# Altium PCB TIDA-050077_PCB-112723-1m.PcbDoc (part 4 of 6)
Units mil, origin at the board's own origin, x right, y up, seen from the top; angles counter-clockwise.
Board outline 3780 x 7750 mil, 16 copper layers (Top Layer, L2-Powet 1, L3-Power 2, L4-Power 3, L5-Power 4, L6-INT 1, L7-INT 2, L8-INT 3, L9-INT 4, L10-INT 5, L11-INT 6, L12-Power 5, L13-Power 6, L14-Power 7, L15-Power 8, Bottom Layer), stack 121.442 mil thick; 381 components, 136 nets, 958 pads, 3470 vias.
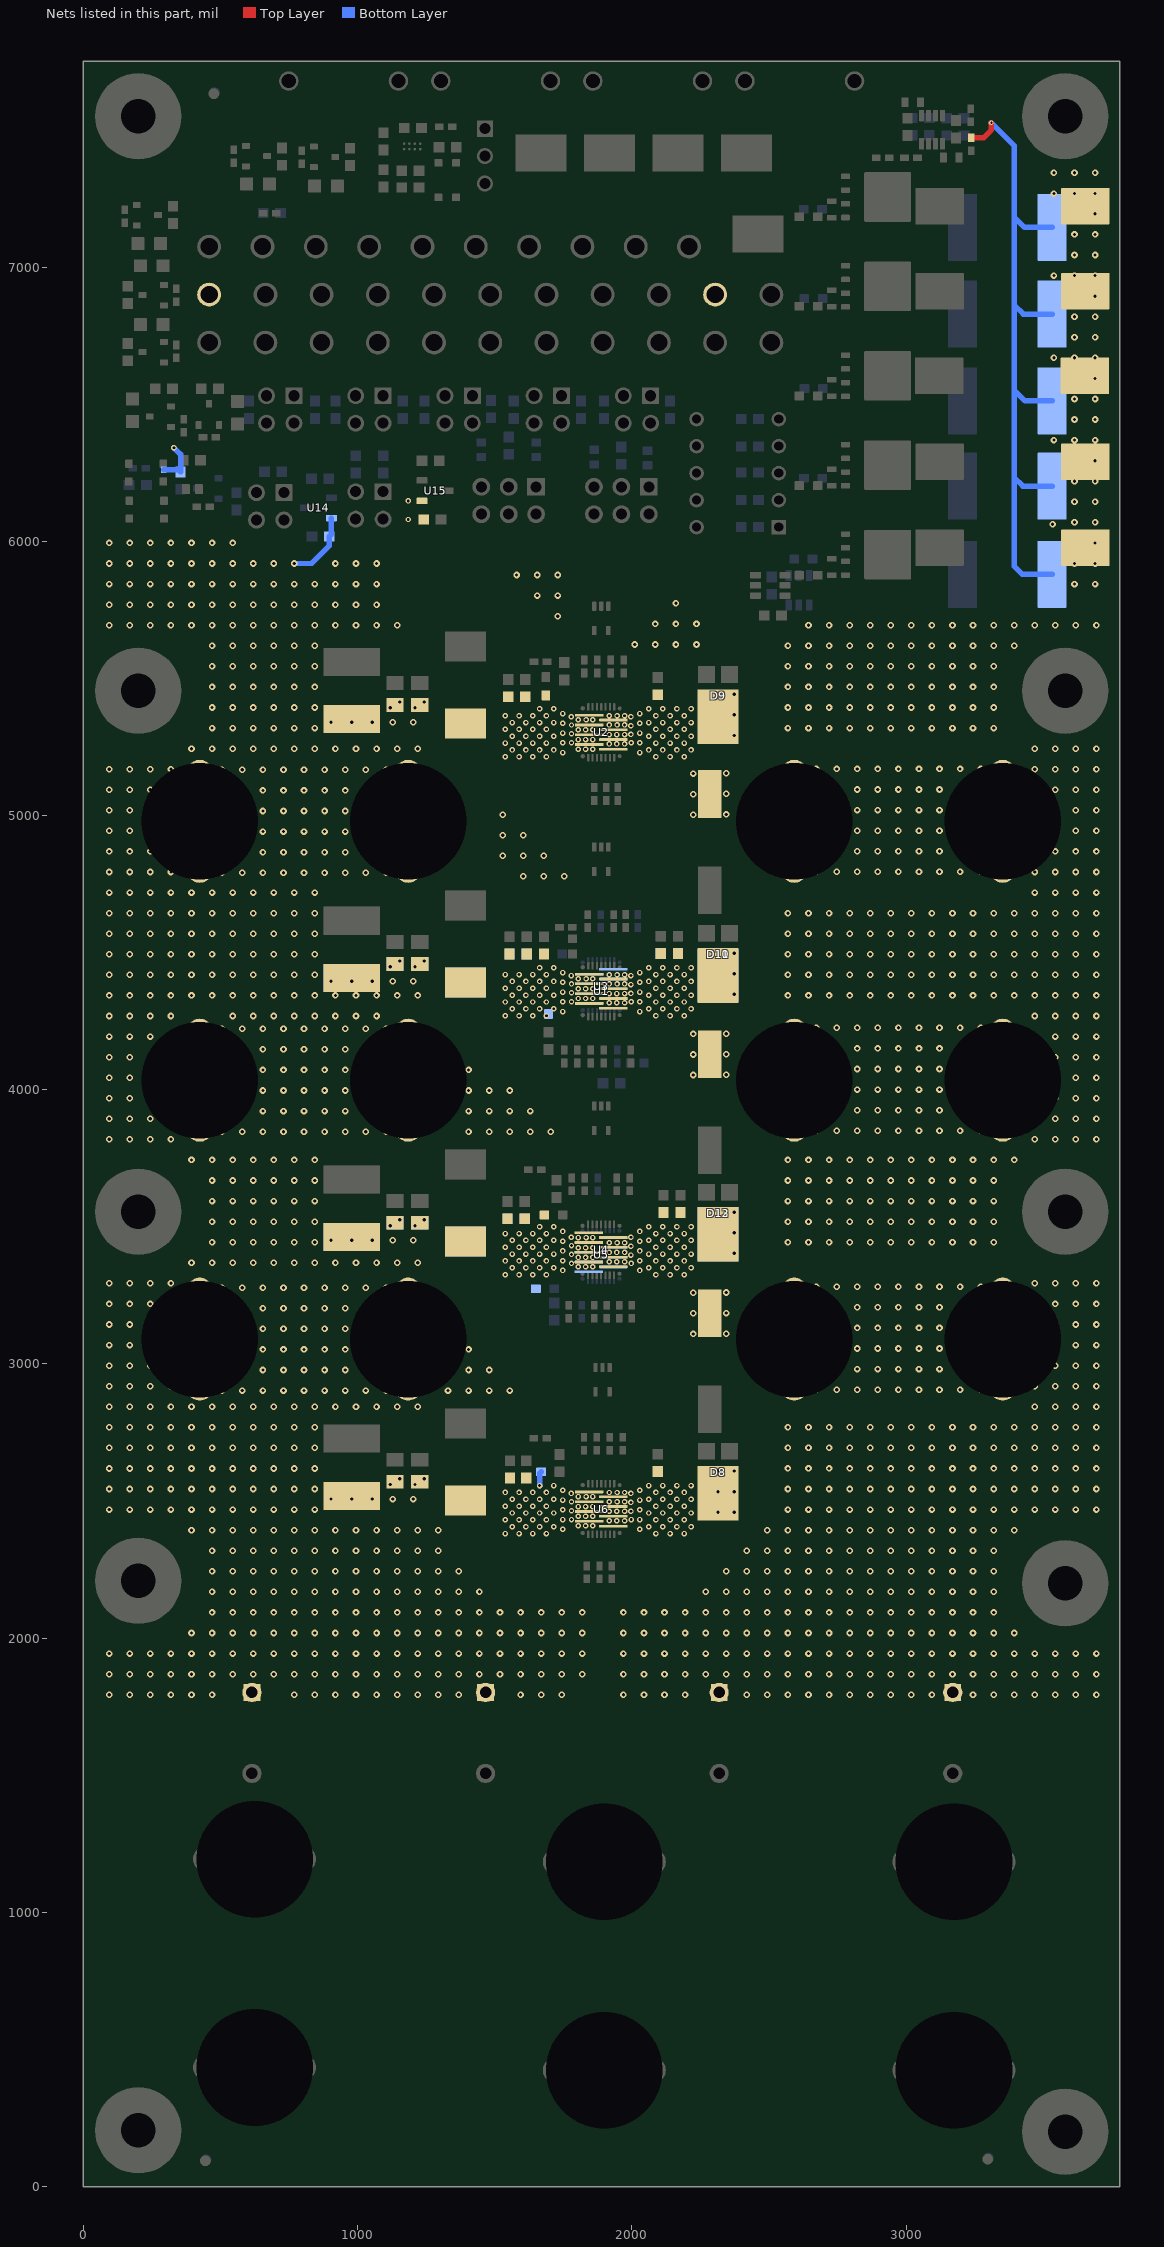
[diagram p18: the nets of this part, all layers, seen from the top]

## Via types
v1: diameter 24, hole 12, Top Layer to Bottom Layer, 2618 vias
v2: diameter 20, hole 10, Top Layer to Bottom Layer, 508 vias
v3: diameter 16, hole 8, Top Layer to Bottom Layer, tented both sides, 135 vias
v4: diameter 24, hole 12.1, Top Layer to Bottom Layer, 125 vias
v5: diameter 20, hole 10, Top Layer to Bottom Layer, tented both sides, 84 vias

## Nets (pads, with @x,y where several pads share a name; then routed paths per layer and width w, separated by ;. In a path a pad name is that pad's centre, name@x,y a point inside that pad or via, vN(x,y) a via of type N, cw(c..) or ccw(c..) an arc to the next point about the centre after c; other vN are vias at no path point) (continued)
VIN: C8.1 C15.1 C19.1 C20.1 C21.1 C31.1 C32.1 C33.1 C34.1 C35.1 C36.1 C37.1 C38.1 C39.1 C40.1 C41.1 C42.1 C43.1 C44.1 C45.1 C46.1 C47.1 C48.1 C49.1 C50.1 C53.1 C54.1 C57.1 C58.1 C61.1 C62.1 C65.1 C66.1 CO6.1 CO7.1 D2.1 D3.1 D4.1 D5.1 D6.1 D7.1 R41.1 R42.2 R46.1 R59.2 R64.2 R69.2 R74.2 R79.2 T5.1 T6.1 T7.1 T14.1 T15.1 TP16.1 U1.23 U1.24 U1.25 U1.26 U2.23 U2.24 U2.25 U2.26 U3.23 U3.24 U3.25 U3.26 U4.23 U4.24 U4.25 U4.26 U5.23 U5.24 U5.25 U5.26 U6.23 U6.24 U6.25 U6.26 U14.2 U15.2 | length 472.9
  Bottom Layer w20: R42.2@292.74,6259.99 347.42,6259.99 R46.1@354.41,6253 354.41,6316.63 v5(330.44,6340.61) ; v1(769.28,5918.9) 832.03,5918.9 896.5,5983.36 C8.1@896.5,6017.04 904.49,6025.04 U14.2@904.49,6084.64 ; v2(1663.71,2556.46) 1663.71,2601.32 R79.2@1668.95,2606.56
  other v1: 94.28,1793.9 169.28,1793.9 244.28,1793.9 319.28,1793.9 394.28,1793.9 469.28,1793.9 769.28,1793.9 844.28,1793.9 919.28,1793.9 994.28,1793.9 1069.28,1793.9 1144.28,1793.9 1219.28,1793.9 1294.28,1793.9 1369.28,1793.9 1594.28,1793.9 1669.28,1793.9 1744.28,1793.9 94.28,1868.9 169.28,1868.9 244.28,1868.9 319.28,1868.9 394.28,1868.9 469.28,1868.9 544.28,1868.9 619.28,1868.9 694.28,1868.9 769.28,1868.9 844.28,1868.9 919.28,1868.9 994.28,1868.9 1069.28,1868.9 1144.28,1868.9 1219.28,1868.9 1294.28,1868.9 1369.28,1868.9 1444.28,1868.9 1519.28,1868.9 1594.28,1868.9 1669.28,1868.9 1744.28,1868.9 1819.28,1868.9 94.28,1943.9 169.28,1943.9 244.28,1943.9 319.28,1943.9 394.28,1943.9 469.28,1943.9 544.28,1943.9 619.28,1943.9 694.28,1943.9 769.28,1943.9 844.28,1943.9 919.28,1943.9 994.28,1943.9 1069.28,1943.9 1144.28,1943.9 1219.28,1943.9 1294.28,1943.9 1369.28,1943.9 1444.28,1943.9 1519.28,1943.9 1594.28,1943.9 1669.28,1943.9 1744.28,1943.9 1819.28,1943.9 394.28,2018.9 469.28,2018.9 544.28,2018.9 619.28,2018.9 694.28,2018.9 769.28,2018.9 844.28,2018.9 919.28,2018.9 994.28,2018.9 1069.28,2018.9 1144.28,2018.9 1219.28,2018.9 1294.28,2018.9 1369.28,2018.9 1444.28,2018.9 1519.28,2018.9 1594.28,2018.9 1669.28,2018.9 1744.28,2018.9 1819.28,2018.9 469.28,2093.9 544.28,2093.9 619.28,2093.9 694.28,2093.9 769.28,2093.9 844.28,2093.9 919.28,2093.9 994.28,2093.9 1069.28,2093.9 1144.28,2093.9 1219.28,2093.9 1294.28,2093.9 1369.28,2093.9 1444.28,2093.9 1519.28,2093.9 1594.28,2093.9 1669.28,2093.9 1744.28,2093.9 1819.28,2093.9 469.28,2168.9 544.28,2168.9 619.28,2168.9 694.28,2168.9 769.28,2168.9 844.28,2168.9 919.28,2168.9 994.28,2168.9 1069.28,2168.9 1144.28,2168.9 1219.28,2168.9 1294.28,2168.9 1369.28,2168.9 1444.28,2168.9 469.28,2243.9 544.28,2243.9 619.28,2243.9 694.28,2243.9 769.28,2243.9 844.28,2243.9 919.28,2243.9 994.28,2243.9 1069.28,2243.9 1144.28,2243.9 1219.28,2243.9 1294.28,2243.9 1369.28,2243.9 469.28,2318.9 544.28,2318.9 619.28,2318.9 694.28,2318.9 769.28,2318.9 844.28,2318.9 919.28,2318.9 994.28,2318.9 1069.28,2318.9 1144.28,2318.9 1219.28,2318.9 1294.28,2318.9 394.28,2393.9 469.28,2393.9 544.28,2393.9 619.28,2393.9 694.28,2393.9 769.28,2393.9 844.28,2393.9 919.28,2393.9 994.28,2393.9 1069.28,2393.9 1144.28,2393.9 1219.28,2393.9 1294.28,2393.9 94.28,2468.9 169.28,2468.9 244.28,2468.9 319.28,2468.9 394.28,2468.9 469.28,2468.9 544.28,2468.9 619.28,2468.9 694.28,2468.9 769.28,2468.9 844.28,2468.9 903.28,2507.32 978.28,2507.32 1053.28,2507.32 1128.28,2507.32 1203.27,2507.32 94.28,2543.9 169.28,2543.9 244.28,2543.9 319.28,2543.9 394.28,2543.9 469.28,2543.9 544.28,2543.9 619.28,2543.9 694.28,2543.9 769.28,2543.9 844.28,2543.9 1119.47,2560.1 1209.47,2560.1 1153.57,2581.23 1243.57,2581.23 94.28,2618.9 169.28,2618.9 244.28,2618.9 319.28,2618.9 394.28,2618.9 469.28,2618.9 544.28,2618.9 619.28,2618.9 694.28,2618.9 769.28,2618.9 844.28,2618.9 94.28,2693.9 169.28,2693.9 244.28,2693.9 319.28,2693.9 394.28,2693.9 469.28,2693.9 544.28,2693.9 619.28,2693.9 694.28,2693.9 769.28,2693.9 844.28,2693.9 94.28,2768.9 169.28,2768.9 244.28,2768.9 319.28,2768.9 394.28,2768.9 469.28,2768.9 544.28,2768.9 619.28,2768.9 694.28,2768.9 769.28,2768.9 844.28,2768.9 94.28,2843.9 169.28,2843.9 244.28,2843.9 319.28,2843.9 394.28,2843.9 469.28,2843.9 544.28,2843.9 619.28,2843.9 694.28,2843.9 769.28,2843.9 844.28,2843.9 919.28,2843.9 994.28,2843.9 1069.28,2843.9 1144.28,2843.9 1219.28,2843.9 504.68,2903 579.68,2903 654.68,2903 729.68,2903 804.68,2903.01 879.68,2903.01 954.68,2903.01 1029.68,2903.01 1104.68,2903.01 1329.68,2903.01 1404.68,2903.01 1479.68,2903.01 1554.68,2903.01 94.28,2918.9 169.28,2918.9 244.28,2918.9 319.28,2918.9 504.68,2978 579.68,2978 654.68,2978 729.68,2978 804.68,2978.01 879.68,2978.01 954.68,2978.01 1029.68,2978.01 1104.68,2978.01 1329.68,2978.01 1404.68,2978.01 1479.68,2978.01 94.28,2993.9 169.28,2993.9 244.28,2993.9 319.28,2993.9 504.68,3053 579.68,3053 654.68,3053 729.68,3053.01 804.68,3053.01 879.68,3053.01 954.68,3053.01 1029.68,3053.01 1104.68,3053.01 1329.68,3053.01 1404.68,3053.01 94.28,3068.9 169.28,3068.9 244.28,3068.9 319.28,3068.9 504.68,3128 579.68,3128 654.68,3128.01 729.68,3128.01 804.68,3128.01 879.68,3128.01 954.68,3128.01 1029.68,3128.01 1104.68,3128.01 1329.68,3128.01 94.28,3143.9 169.28,3143.9 244.28,3143.9 319.28,3143.9 504.68,3203 579.68,3203 654.68,3203.01 729.68,3203.01 804.68,3203.01 879.68,3203.01 954.68,3203.01 1029.68,3203.01 1104.68,3203.01 94.28,3218.9 169.28,3218.9 244.28,3218.9 319.28,3218.9 504.68,3278 579.68,3278.01 654.68,3278.01 729.68,3278.01 804.68,3278.01 879.68,3278.01 954.68,3278.01 1029.68,3278.01 1104.68,3278.01 94.28,3293.9 169.28,3293.9 244.28,3293.9 319.28,3293.9 394.28,3368.9 469.28,3368.9 544.28,3368.9 619.28,3368.9 694.28,3368.9 769.28,3368.9 844.28,3368.9 919.28,3368.9 994.28,3368.9 1069.28,3368.9 1144.28,3368.9 1219.28,3368.9 469.28,3443.9 544.28,3443.9 619.28,3443.9 694.28,3443.9 769.28,3443.9 844.28,3443.9 903.28,3451.51 978.28,3451.51 1053.28,3451.51 1128.28,3451.51 1203.27,3451.51 1119.47,3504.29 1209.47,3504.29 469.28,3518.9 544.28,3518.9 619.28,3518.9 694.28,3518.9 769.28,3518.9 844.28,3518.9 1153.57,3525.42 1243.57,3525.42 469.28,3593.9 544.28,3593.9 619.28,3593.9 694.28,3593.9 769.28,3593.9 844.28,3593.9 469.28,3668.9 544.28,3668.9 619.28,3668.9 694.28,3668.9 769.28,3668.9 844.28,3668.9 394.28,3743.9 469.28,3743.9 544.28,3743.9 619.28,3743.9 694.28,3743.9 769.28,3743.9 844.28,3743.9 94.28,3818.9 169.28,3818.9 244.28,3818.9 319.28,3818.9 504.68,3847.2 579.68,3847.2 654.68,3847.2 729.68,3847.2 804.68,3847.2 879.68,3847.2 954.68,3847.2 1029.68,3847.2 1104.68,3847.2 1404.68,3847.2 1479.68,3847.2 1554.68,3847.2 1629.68,3847.2 1704.68,3847.2 94.28,3893.9 169.28,3893.9 244.28,3893.9 319.28,3893.9 504.68,3922.2 579.68,3922.2 654.68,3922.2 729.68,3922.2 804.68,3922.2 879.68,3922.2 954.68,3922.2 1029.68,3922.2 1104.68,3922.2 1404.68,3922.2 1479.68,3922.2 1554.68,3922.2 1629.68,3922.2 94.28,3968.9 169.28,3968.9 244.28,3968.9 319.28,3968.9 504.68,3997.2 579.68,3997.2 654.68,3997.2 729.68,3997.2 804.68,3997.2 879.68,3997.2 954.68,3997.2 1029.68,3997.2 1104.68,3997.2 1404.68,3997.2 1479.68,3997.2 1554.68,3997.2 94.28,4043.9 169.28,4043.9 244.28,4043.9 319.28,4043.9 504.68,4072.2 579.68,4072.2 654.68,4072.2 729.68,4072.2 804.68,4072.2 879.68,4072.2 954.68,4072.2 1029.68,4072.2 1104.68,4072.2 1404.68,4072.2 94.28,4118.9 169.28,4118.9 244.28,4118.9 319.28,4118.9 504.68,4147.2 579.68,4147.2 654.68,4147.2 729.68,4147.2 804.68,4147.2 879.68,4147.2 954.68,4147.2 1029.68,4147.2 1104.68,4147.2 94.28,4193.9 169.28,4193.9 244.28,4193.9 319.28,4193.9 504.68,4222.2 579.68,4222.2 654.68,4222.2 729.68,4222.2 804.68,4222.2 879.68,4222.2 954.68,4222.2 1029.68,4222.2 1104.68,4222.2 94.28,4268.9 169.28,4268.9 244.28,4268.9 319.28,4268.9 544.28,4268.9 619.28,4268.9 694.28,4268.9 769.28,4268.9 844.28,4268.9 919.28,4268.9 994.28,4268.9 1069.28,4268.9 94.28,4343.9 169.28,4343.9 244.28,4343.9 319.28,4343.9 394.28,4343.9 469.28,4343.9 544.28,4343.9 619.28,4343.9 694.28,4343.9 769.28,4343.9 844.28,4343.9 919.28,4343.9 994.28,4343.9 1069.28,4343.9 1144.28,4343.9 1219.28,4343.9 903.28,4395.71 978.28,4395.71 1053.28,4395.71 1128.28,4395.71 1203.28,4395.71 94.28,4418.9 169.28,4418.9 244.28,4418.9 319.28,4418.9 394.28,4418.9 469.28,4418.9 544.28,4418.9 619.28,4418.9 694.28,4418.9 769.28,4418.9 844.28,4418.9 1119.47,4448.49 1209.47,4448.49 1153.57,4469.62 1243.57,4469.62 94.28,4493.9 169.28,4493.9 244.28,4493.9 319.28,4493.9 394.28,4493.9 469.28,4493.9 544.28,4493.9 619.28,4493.9 694.28,4493.9 769.28,4493.9 844.28,4493.9 94.28,4568.9 169.28,4568.9 244.28,4568.9 319.28,4568.9 394.28,4568.9 469.28,4568.9 544.28,4568.9 619.28,4568.9 694.28,4568.9 769.28,4568.9 844.28,4568.9 94.28,4643.9 169.28,4643.9 244.28,4643.9 319.28,4643.9 394.28,4643.9 469.28,4643.9 544.28,4643.9 619.28,4643.9 694.28,4643.9 769.28,4643.9 844.28,4643.9 94.28,4718.9 169.28,4718.9 244.28,4718.9 319.28,4718.9 394.28,4718.9 469.28,4718.9 544.28,4718.9 619.28,4718.9 694.28,4718.9 769.28,4718.9 844.28,4718.9 1603.98,4777.96 1678.98,4777.96 1753.98,4777.96 504.68,4791.4 579.68,4791.4 654.68,4791.4 729.68,4791.4 804.68,4791.4 879.68,4791.4 954.68,4791.4 1029.68,4791.4 1104.68,4791.4 94.28,4793.9 169.28,4793.9 244.28,4793.9 319.28,4793.9 1528.98,4852.96 1603.98,4852.96 1678.98,4852.96 504.68,4866.4 579.68,4866.4 654.68,4866.4 729.68,4866.4 804.68,4866.4 879.68,4866.4 954.68,4866.4 1029.68,4866.4 1104.68,4866.4 94.28,4868.9 169.28,4868.9 244.28,4868.9 319.28,4868.9 1528.98,4927.96 1603.98,4927.96 504.68,4941.4 579.68,4941.4 654.68,4941.4 729.68,4941.4 804.68,4941.4 879.68,4941.4 954.68,4941.4 1029.68,4941.4 1104.68,4941.4 94.28,4943.9 169.28,4943.9 244.28,4943.9 319.28,4943.9 1528.98,5002.96 504.68,5016.4 579.68,5016.4 654.68,5016.4 729.68,5016.4 804.68,5016.4 879.68,5016.4 954.68,5016.4 1029.68,5016.4 1104.68,5016.4 94.28,5018.9 169.28,5018.9 244.28,5018.9 319.28,5018.9 504.68,5091.4 579.68,5091.4 654.68,5091.4 729.68,5091.4 804.68,5091.4 879.68,5091.4 954.68,5091.4 1029.68,5091.4 1104.68,5091.4 94.28,5093.9 169.28,5093.9 244.28,5093.9 319.28,5093.9 504.68,5166.4 579.68,5166.4 654.68,5166.4 729.68,5166.4 804.68,5166.4 879.68,5166.4 954.68,5166.4 1029.68,5166.4 1104.68,5166.4 94.28,5168.9 169.28,5168.9 244.28,5168.9 319.28,5168.9 394.28,5243.9 469.28,5243.9 544.28,5243.9 619.28,5243.9 694.28,5243.9 769.28,5243.9 844.28,5243.9 919.28,5243.9 994.28,5243.9 1069.28,5243.9 1144.28,5243.9 1219.28,5243.9 469.28,5318.9 544.28,5318.9 619.28,5318.9 694.28,5318.9 769.28,5318.9 844.28,5318.9 903.28,5339.91 978.28,5339.91 1053.28,5339.91 1128.28,5339.91 1203.27,5339.91 1119.47,5392.69 1209.47,5392.69 469.28,5393.9 544.28,5393.9 619.28,5393.9 694.28,5393.9 769.28,5393.9 844.28,5393.9 1153.57,5413.81 1243.57,5413.81 469.28,5468.9 544.28,5468.9 619.28,5468.9 694.28,5468.9 769.28,5468.9 844.28,5468.9 469.28,5543.9 544.28,5543.9 619.28,5543.9 694.28,5543.9 769.28,5543.9 844.28,5543.9 469.28,5618.9 544.28,5618.9 619.28,5618.9 694.28,5618.9 769.28,5618.9 844.28,5618.9 94.28,5693.9 169.28,5693.9 244.28,5693.9 319.28,5693.9 394.28,5693.9 469.28,5693.9 544.28,5693.9 619.28,5693.9 694.28,5693.9 769.28,5693.9 844.28,5693.9 919.28,5693.9 994.28,5693.9 1069.28,5693.9 1144.28,5693.9 1729.73,5726.9 94.28,5768.9 169.28,5768.9 244.28,5768.9 319.28,5768.9 394.28,5768.9 469.28,5768.9 544.28,5768.9 619.28,5768.9 694.28,5768.9 769.28,5768.9 844.28,5768.9 919.28,5768.9 994.28,5768.9 1069.28,5768.9 1654.73,5801.9 1729.73,5801.9 94.28,5843.9 169.28,5843.9 244.28,5843.9 319.28,5843.9 394.28,5843.9 469.28,5843.9 544.28,5843.9 619.28,5843.9 694.28,5843.9 769.28,5843.9 844.28,5843.9 919.28,5843.9 994.28,5843.9 1069.28,5843.9 1579.73,5876.9 1654.73,5876.9 1729.73,5876.9 94.28,5918.9 169.28,5918.9 244.28,5918.9 319.28,5918.9 394.28,5918.9 469.28,5918.9 544.28,5918.9 619.28,5918.9 694.28,5918.9 919.28,5918.9 994.28,5918.9 1069.28,5918.9 94.28,5993.9 169.28,5993.9 244.28,5993.9 319.28,5993.9 394.28,5993.9 469.28,5993.9 544.28,5993.9
  other v2: 1538.71,2381.46 1588.71,2381.46 1638.71,2381.46 1688.71,2381.46 1748.06,2396.79 1563.71,2406.46 1613.71,2406.46 1663.71,2406.46 1715.22,2406.46 1804.75,2409.62 1831.28,2409.62 1857.82,2409.62 1538.71,2431.46 1588.71,2431.46 1638.71,2431.46 1688.71,2431.46 1748.06,2432.35 1780.04,2432.35 1804.75,2444.25 1831.28,2444.25 1857.82,2444.25 1563.71,2456.46 1613.71,2456.46 1663.71,2456.46 1715.22,2456.46 1780.04,2465.13 1748.06,2467.91 1804.75,2479.87 1831.28,2479.87 1857.82,2479.87 1538.71,2481.46 1588.71,2481.46 1638.71,2481.46 1688.71,2481.46 1780.04,2497.39 1748.06,2503.47 1563.71,2506.46 1613.71,2506.46 1663.71,2506.46 1715.22,2506.46 1804.75,2516.48 1832.94,2516.48 1857.82,2516.48 1779.29,2527.85 1538.71,2531.46 1588.71,2531.46 1638.71,2531.46 1688.71,2531.46 1748.06,2539.03 1715.22,2556.46 1538.71,3325.66 1588.71,3325.66 1638.71,3325.66 1688.71,3325.66 1748.06,3340.99 1563.71,3350.66 1613.71,3350.66 1663.71,3350.66 1715.22,3350.66 1804.75,3354.83 1831.28,3354.83 1857.82,3354.83 1780.04,3366.55 1538.71,3375.66 1588.71,3375.66 1638.71,3375.66 1688.71,3375.66 1748.06,3376.55 1804.75,3388.45 1831.28,3388.45 1857.82,3388.45 1780.04,3399.33 1563.71,3400.66 1613.71,3400.66 1663.71,3400.66 1715.22,3400.66 1748.06,3412.1 1804.75,3424.07 1831.28,3424.07 1857.82,3424.07 1538.71,3425.66 1588.71,3425.66 1638.71,3425.66 1688.71,3425.66 1780.04,3431.58 1748.06,3447.66 1563.71,3450.66 1613.71,3450.66 1663.71,3450.66 1715.22,3450.66 1804.75,3460.68 1832.94,3460.68 1857.82,3460.68 1779.29,3462.05 1538.71,3475.66 1588.71,3475.66 1638.71,3475.66 1688.71,3475.66 1748.06,3483.22 1663.71,3500.66 1715.22,3500.66 1538.71,4269.86 1588.71,4269.86 1638.71,4269.86 1688.71,4269.86 1748.06,4285.18 1563.71,4294.86 1613.71,4294.86 1663.71,4294.86 1715.22,4294.86 1538.71,4319.86 1588.71,4319.86 1638.71,4319.86 1688.71,4319.86 1748.06,4320.74 1780.04,4320.74 1804.75,4332.64 1831.28,4332.64 1857.82,4332.64 1563.71,4344.86 1613.71,4344.86 1663.71,4344.86 1715.22,4344.86 1780.04,4353.52 1748.06,4356.3 1804.75,4368.26 1831.28,4368.26 1857.82,4368.26 1538.71,4369.86 1588.71,4369.86 1638.71,4369.86 1688.71,4369.86 1780.04,4385.78 1748.06,4391.86 1563.71,4394.86 1613.71,4394.86 1663.71,4394.86 1715.22,4394.86 1804.75,4404.87 1832.94,4404.87 1857.82,4404.87 1779.29,4416.24 1538.71,4419.86 1588.71,4419.86 1638.71,4419.86 1688.71,4419.86 1748.06,4427.42 1663.71,4444.86 1715.22,4444.86 1538.71,5214.05 1588.71,5214.05 1638.71,5214.05 1688.71,5214.05 1748.06,5229.38 1563.71,5239.05 1613.71,5239.05 1663.71,5239.05 1715.22,5239.05 1804.75,5241.21 1831.28,5241.21 1857.82,5241.21 1538.71,5264.05 1588.71,5264.05 1638.71,5264.05 1688.71,5264.05 1748.06,5264.94 1780.04,5264.94 1804.75,5276.84 1831.28,5276.84 1857.82,5276.84 1563.71,5289.05 1613.71,5289.05 1663.71,5289.05 1715.22,5289.05 1780.04,5297.72 1748.06,5300.5 1804.75,5312.46 1831.28,5312.46 1857.82,5312.46 1538.71,5314.05 1588.71,5314.05 1638.71,5314.05 1688.71,5314.05 1780.04,5329.97 1748.06,5336.05 1563.71,5339.05 1613.71,5339.05 1663.71,5339.05 1715.22,5339.05 1804.75,5349.07 1832.94,5349.07 1857.82,5349.07 1779.29,5360.44 1538.71,5364.05 1588.71,5364.05 1638.71,5364.05 1688.71,5364.05 1748.06,5371.61 1663.71,5389.05 1715.22,5389.05
  other v5: 1184.33,6079.37 1184.33,6146.97
VOUT: C22.1 C23.1 C24.1 C51.1 C55.1 C59.1 C63.1 C67.1 CO1.1 CO2.1 CO3.1 CO4.1 CO5.1 D8.3 D9.3 D10.3 D11.3 D12.3 D13.3 R23.2 R24.2 R25.2 R26.2 R27.2 R28.2 R29.2 R30.2 R31.2 R32.2 RZ1.2 T1.1 T2.1 T8.1 T9.1 T10.1 TP22.1 U1.10 U1.11 U1.12 U1.13 U2.10 U2.11 U2.12 U2.13 U3.10 U3.11 U3.12 U3.13 U4.10 U4.11 U4.12 U4.13 U5.10 U5.11 U5.12 U5.13 U6.10 U6.11 U6.12 U6.13 | length 2525.6
  Top Layer w20: RZ1.2@3237.75,7471.09 3282.31,7471.09 3311.29,7500.08 v3(3311.29,7526.09)
  Bottom Layer w20: v3(3311.29,7526.09) 3394.28,7443.1 3394.28,7182.75 ; R31.2@3532.55,5879.5 3424.33,5879.5 3394.28,5909.55 3394.28,6232.49 ; R30.2@3532.55,6200.81 3425.96,6200.81 3394.28,6232.49 ; R29.2@3532.55,6512.12 3434.49,6512.12 3394.28,6552.33 ; R28.2@3532.55,6828.44 3427.57,6828.44 3394.28,6861.73 ; R32.2@3532.55,7144.75 3432.28,7144.75 3394.28,7182.75 ; 3394.28,6232.49 3394.28,6552.33 ; 3394.28,6552.33 3394.28,6861.73 ; 3394.28,6861.73 3394.28,7182.75
  other v1: 1969.28,1793.91 2044.28,1793.91 2119.28,1793.91 2194.28,1793.91 2419.28,1793.91 2494.28,1793.91 2569.28,1793.91 2644.28,1793.91 2719.28,1793.91 2794.28,1793.91 2869.28,1793.91 2944.28,1793.91 3019.28,1793.91 3094.28,1793.91 3244.28,1793.91 3319.28,1793.91 3394.28,1793.91 3469.28,1793.91 3544.28,1793.91 3619.28,1793.91 3694.28,1793.91 1969.28,1868.91 2044.28,1868.91 2119.28,1868.91 2194.28,1868.91 2269.28,1868.91 2344.28,1868.91 2419.28,1868.91 2494.28,1868.91 2569.28,1868.91 2644.28,1868.91 2719.28,1868.91 2794.28,1868.91 2869.28,1868.91 2944.28,1868.91 3019.28,1868.91 3094.28,1868.91 3169.28,1868.91 3244.28,1868.91 3319.28,1868.91 3394.28,1868.91 3469.28,1868.91 3544.28,1868.91 3619.28,1868.91 3694.28,1868.91 1969.28,1943.91 2044.28,1943.91 2119.28,1943.91 2194.28,1943.91 2269.28,1943.91 2344.28,1943.91 2419.28,1943.91 2494.28,1943.91 2569.28,1943.91 2644.28,1943.91 2719.28,1943.91 2794.28,1943.91 2869.28,1943.91 2944.28,1943.91 3019.28,1943.91 3094.28,1943.91 3169.28,1943.91 3244.28,1943.91 3319.28,1943.91 3394.28,1943.91 3469.28,1943.91 3544.28,1943.91 3619.28,1943.91 3694.28,1943.91 1969.28,2018.91 2044.28,2018.91 2119.28,2018.91 2194.28,2018.91 2269.28,2018.91 2344.28,2018.91 2419.28,2018.91 2494.28,2018.91 2569.28,2018.91 2644.28,2018.91 2719.28,2018.91 2794.28,2018.91 2869.28,2018.91 2944.28,2018.91 3019.28,2018.91 3094.28,2018.91 3169.28,2018.91 3244.28,2018.91 3319.28,2018.91 3394.28,2018.91 1969.28,2093.91 2044.28,2093.91 2119.28,2093.91 2194.28,2093.91 2269.28,2093.91 2344.28,2093.91 2419.28,2093.91 2494.28,2093.91 2569.28,2093.91 2644.28,2093.91 2719.28,2093.91 2794.28,2093.91 2869.28,2093.91 2944.28,2093.91 3019.28,2093.91 3094.28,2093.91 3169.28,2093.91 3244.28,2093.91 3319.28,2093.91 2269.28,2168.91 2344.28,2168.91 2419.28,2168.91 2494.28,2168.91 2569.28,2168.91 2644.28,2168.91 2719.28,2168.91 2794.28,2168.9 2869.28,2168.9 2944.28,2168.9 3019.28,2168.9 3094.28,2168.9 3169.28,2168.9 3244.28,2168.9 3319.28,2168.9 2344.28,2243.9 2419.28,2243.9 2494.28,2243.9 2569.28,2243.9 2644.28,2243.9 2719.28,2243.9 2794.28,2243.9 2869.28,2243.9 2944.28,2243.9 3019.28,2243.9 3094.28,2243.9 3169.28,2243.9 3244.28,2243.9 3319.28,2243.9 2419.28,2318.9 2494.28,2318.9 2569.28,2318.9 2644.28,2318.9 2719.28,2318.9 2794.28,2318.9 2869.28,2318.9 2944.28,2318.9 3019.28,2318.9 3094.28,2318.9 3169.28,2318.9 3244.28,2318.9 3319.28,2318.9 2494.28,2393.9 2569.28,2393.9 2644.28,2393.9 2719.28,2393.9 2794.28,2393.9 2869.28,2393.9 2944.28,2393.9 3019.28,2393.9 3094.28,2393.9 3169.28,2393.9 3244.28,2393.9 3319.28,2393.9 3394.28,2393.9 2314.28,2459.45 2373.55,2459.45 2569.28,2468.9 2644.28,2468.9 2719.28,2468.9 2794.28,2468.9 2869.28,2468.9 2944.28,2468.9 3019.28,2468.9 3094.28,2468.9 3169.28,2468.9 3244.28,2468.9 3319.28,2468.9 3394.28,2468.9 3469.28,2468.9 3544.28,2468.9 3619.28,2468.9 3694.28,2468.9 2314.28,2534.45 2373.55,2534.45 2569.28,2543.9 2644.28,2543.9 2719.28,2543.9 2794.28,2543.9 2869.28,2543.9 2944.28,2543.9 3019.28,2543.9 3094.28,2543.9 3169.28,2543.9 3244.28,2543.9 3319.28,2543.9 3394.28,2543.9 3469.28,2543.9 3544.28,2543.9 3619.28,2543.9 3694.28,2543.9 2314.28,2609.44 2373.55,2609.44 2569.28,2618.9 2644.28,2618.9 2719.28,2618.9 2794.28,2618.9 2869.28,2618.9 2944.28,2618.9 3019.28,2618.9 3094.28,2618.9 3169.28,2618.9 3244.28,2618.9 3319.28,2618.9 3394.28,2618.9 3469.28,2618.9 3544.28,2618.9 3619.28,2618.9 3694.28,2618.9 2569.28,2693.9 2644.28,2693.9 2719.28,2693.9 2794.28,2693.9 2869.28,2693.9 2944.28,2693.9 3019.28,2693.9 3094.28,2693.9 3169.28,2693.9 3244.28,2693.9 3319.28,2693.9 3394.28,2693.9 3469.28,2693.9 3544.28,2693.9 3619.28,2693.9 3694.28,2693.9 2569.28,2768.9 2644.28,2768.9 2719.28,2768.9 2794.28,2768.9 2869.28,2768.9 2944.28,2768.9 3019.28,2768.9 3094.28,2768.9 3169.28,2768.9 3244.28,2768.9 3319.28,2768.9 3394.28,2768.9 3469.28,2768.9 3544.28,2768.9 3619.28,2768.9 3694.28,2768.9 3469.28,2843.9 3544.28,2843.9 3619.28,2843.9 3694.28,2843.9 2672.09,2906.4 2747.09,2906.4 2822.09,2906.4 2897.09,2906.4 2972.1,2906.4 3047.1,2906.4 3122.1,2906.4 3197.1,2906.4 3272.1,2906.4 3469.28,2918.9 3544.28,2918.9 3619.28,2918.9 3694.28,2918.9 2672.09,2981.4 2747.09,2981.4 2822.09,2981.4 2897.09,2981.4 2972.09,2981.4 3047.1,2981.4 3122.1,2981.4 3197.1,2981.4 3272.1,2981.4 3469.28,2993.9 3544.28,2993.9 3619.28,2993.9 3694.28,2993.9 2672.09,3056.4 2747.09,3056.4 2822.09,3056.4 2897.09,3056.4 2972.1,3056.4 3047.1,3056.4 3122.1,3056.4 3197.1,3056.4 3272.1,3056.4 3469.28,3068.9 3544.28,3068.9 3619.28,3068.9 3694.28,3068.9 2224.28,3109.37 2344.28,3110.43 2672.09,3131.4 2747.09,3131.4 2822.09,3131.4 2897.09,3131.4 2972.09,3131.4 3047.1,3131.4 3122.1,3131.4 3197.1,3131.4 3272.1,3131.4 3469.28,3143.9 3544.28,3143.9 3619.28,3143.9 3694.28,3143.9 2224.28,3184.37 2344.28,3185.43 2672.09,3206.4 2747.09,3206.4 2822.09,3206.4 2897.09,3206.4 2972.09,3206.4 3047.09,3206.4 3122.1,3206.4 3197.1,3206.4 3272.1,3206.4 3469.28,3218.9 3544.28,3218.9 3619.28,3218.9 3694.28,3218.9 2224.28,3259.37 2344.28,3260.42 2672.09,3281.4 2747.09,3281.4 2822.09,3281.4 2897.09,3281.4 2972.09,3281.4 3047.1,3281.4 3122.1,3281.4 3197.1,3281.4 3272.1,3281.4 3469.28,3293.9 3544.28,3293.9 3619.28,3293.9 3694.28,3293.9 2373.55,3403.64 2569.28,3443.9 2644.28,3443.9 2719.28,3443.9 2794.28,3443.9 2869.28,3443.9 2944.28,3443.9 3019.28,3443.9 3094.28,3443.9 3169.28,3443.9 3244.28,3443.9 3319.28,3443.9 2373.55,3478.64 2569.28,3518.9 2644.28,3518.9 2719.28,3518.9 2794.28,3518.9 2869.28,3518.9 2944.28,3518.9 3019.28,3518.9 3094.28,3518.9 3169.28,3518.9 3244.28,3518.9 3319.28,3518.9 2373.55,3553.64 2569.28,3593.9 2644.28,3593.9 2719.28,3593.9 2794.28,3593.9 2869.28,3593.9 2944.28,3593.9 3019.28,3593.9 3094.28,3593.9 3169.28,3593.9 3244.28,3593.9 3319.28,3593.9 2569.28,3668.9 2644.28,3668.9 2719.28,3668.9 2794.28,3668.9 2869.28,3668.9 2944.28,3668.9 3019.28,3668.9 3094.28,3668.9 3169.28,3668.9 3244.28,3668.9 3319.28,3668.9 2569.28,3743.9 2644.28,3743.9 2719.28,3743.9 2794.28,3743.9 2869.28,3743.9 2944.28,3743.9 3019.28,3743.9 3094.28,3743.9 3169.28,3743.9 3244.28,3743.9 3319.28,3743.9 3394.28,3743.9 3469.28,3818.9 3544.28,3818.9 3619.28,3818.9 3694.28,3818.9 2672.09,3850.59 2747.09,3850.59 2822.09,3850.59 2897.09,3850.59 2972.1,3850.59 3047.1,3850.59 3122.1,3850.59 3197.1,3850.59 3272.1,3850.59 3469.28,3893.9 3544.28,3893.9 3619.28,3893.9 3694.28,3893.9 2672.09,3925.59 2747.09,3925.59 2822.09,3925.59 2897.09,3925.59 2972.09,3925.59 3047.1,3925.59 3122.1,3925.59 3197.1,3925.59 3272.1,3925.59 3469.28,3968.9 3544.28,3968.9 3619.28,3968.9 3694.28,3968.9 2672.09,4000.59 2747.09,4000.59 2822.09,4000.59 2897.09,4000.59 2972.1,4000.59 3047.1,4000.59 3122.1,4000.59 3197.1,4000.59 3272.1,4000.59 3469.28,4043.9 3544.28,4043.9 3619.28,4043.9 3694.28,4043.9 2224.28,4053.57 2344.28,4054.62 2672.09,4075.59 2747.09,4075.59 2822.09,4075.59 2897.09,4075.59 2972.09,4075.59 3047.1,4075.59 3122.1,4075.59 3197.1,4075.59 3272.1,4075.59 3469.28,4118.9 3544.28,4118.9 3619.28,4118.9 3694.28,4118.9 2224.28,4128.57 2344.28,4129.62 2672.09,4150.59 2747.09,4150.59 2822.09,4150.59 2897.09,4150.59 2972.09,4150.59 3047.09,4150.59 3122.1,4150.59 3197.1,4150.59 3272.1,4150.59 3469.28,4193.9 3544.28,4193.9 3619.28,4193.9 3694.28,4193.9 2224.28,4203.57 2344.28,4204.62 2672.09,4225.59 2747.09,4225.59 2822.09,4225.59 2897.09,4225.59 2972.09,4225.59 3047.1,4225.59 3122.1,4225.59 3197.1,4225.59 3272.1,4225.59 3469.28,4268.9 3544.28,4268.9 3619.28,4268.9 3694.28,4268.9 2569.28,4343.9 2644.28,4343.9 2719.28,4343.9 2794.28,4343.9 2869.28,4343.9 2944.28,4343.9 3019.28,4343.9 3094.28,4343.9 3169.28,4343.9 3244.28,4343.9 3319.28,4343.9 3394.28,4343.9 3469.28,4343.9 3544.28,4343.9 3619.28,4343.9 3694.28,4343.9 2373.55,4347.84 2569.28,4418.9 2644.28,4418.9 2719.28,4418.9 2794.28,4418.9 2869.28,4418.9 2944.28,4418.9 3019.28,4418.9 3094.28,4418.9 3169.28,4418.9 3244.28,4418.9 3319.28,4418.9 3394.28,4418.9 3469.28,4418.9 3544.28,4418.9 3619.28,4418.9 3694.28,4418.9 2373.55,4422.84 2569.28,4493.9 2644.28,4493.9 2719.28,4493.9 2794.28,4493.9 2869.28,4493.9 2944.28,4493.9 3019.28,4493.9 3094.28,4493.9 3169.28,4493.9 3244.28,4493.9 3319.28,4493.9 3394.28,4493.9 3469.28,4493.9 3544.28,4493.9 3619.28,4493.9 3694.28,4493.9 2373.55,4497.83 2569.28,4568.9 2644.28,4568.9 2719.28,4568.9 2794.28,4568.9 2869.28,4568.9 2944.28,4568.9 3019.28,4568.9 3094.28,4568.9 3169.28,4568.9 3244.28,4568.9 3319.28,4568.9 3394.28,4568.9 3469.28,4568.9 3544.28,4568.9 3619.28,4568.9 3694.28,4568.9 2569.28,4643.9 2644.28,4643.9 2719.28,4643.9 2794.28,4643.9 2869.28,4643.9 2944.28,4643.9 3019.28,4643.9 3094.28,4643.9 3169.28,4643.9 3244.28,4643.9 3319.28,4643.9 3394.28,4643.9 3469.28,4643.9 3544.28,4643.9 3619.28,4643.9 3694.28,4643.9 3469.28,4718.9 3544.28,4718.9 3619.28,4718.9 3694.28,4718.9 3469.28,4793.9 3544.28,4793.9 3619.28,4793.9 3694.28,4793.9 2672.09,4794.79 2747.09,4794.79 2822.09,4794.79 2897.09,4794.79 2972.1,4794.79 3047.1,4794.79 3122.1,4794.79 3197.1,4794.79 3272.1,4794.79 3469.28,4868.9 3544.28,4868.9 3619.28,4868.9 3694.28,4868.9 2672.09,4869.79 2747.09,4869.79 2822.09,4869.79 2897.09,4869.79 2972.09,4869.79 3047.1,4869.79 3122.1,4869.79 3197.1,4869.79 3272.1,4869.79 3469.28,4943.9 3544.28,4943.9 3619.28,4943.9 3694.28,4943.9 2672.09,4944.79 2747.09,4944.79 2822.09,4944.79 2897.09,4944.79 2972.1,4944.79 3047.1,4944.79 3122.1,4944.79 3197.1,4944.79 3272.1,4944.79 2224.28,5002.84 2344.28,5003.9 3469.28,5018.9 3544.28,5018.9 3619.28,5018.9 3694.28,5018.9 2672.09,5019.79 2747.09,5019.79 2822.09,5019.79 2897.09,5019.79 2972.09,5019.79 3047.1,5019.79 3122.1,5019.79 3197.1,5019.79 3272.1,5019.79 2224.28,5077.84 2344.28,5078.9 3469.28,5093.9 3544.28,5093.9 3619.28,5093.9 3694.28,5093.9 2672.09,5094.79 2747.09,5094.79 2822.09,5094.79 2897.09,5094.79 2972.09,5094.79 3047.09,5094.79 3122.1,5094.79 3197.1,5094.79 3272.1,5094.79 2224.28,5152.84 2344.28,5153.9 3469.28,5168.9 3544.28,5168.9 3619.28,5168.9 3694.28,5168.9 2672.09,5169.79 2747.09,5169.79 2822.09,5169.79 2897.09,5169.79 2972.09,5169.79 3047.1,5169.79 3122.1,5169.79 3197.1,5169.79 3272.1,5169.79 3469.28,5243.9 3544.28,5243.9 3619.28,5243.9 3694.28,5243.9 2373.55,5292.04 2569.28,5318.9 2644.28,5318.9 2719.28,5318.9 2794.28,5318.9 2869.28,5318.9 2944.28,5318.9 3019.28,5318.9 3094.28,5318.9 3169.28,5318.9 3244.28,5318.9 3319.28,5318.9 2373.55,5367.03 2569.28,5393.9 2644.28,5393.9 2719.28,5393.9 2794.28,5393.9 2869.28,5393.9 2944.28,5393.9 3019.28,5393.9 3094.28,5393.9 3169.28,5393.9 3244.28,5393.9 3319.28,5393.9 2373.55,5442.03 2569.28,5468.9 2644.28,5468.9 2719.28,5468.9 2794.28,5468.9 2869.28,5468.9 2944.28,5468.9 3019.28,5468.9 3094.28,5468.9 3169.28,5468.9 3244.28,5468.9 3319.28,5468.9 2569.28,5543.9 2644.28,5543.9 2719.28,5543.9 2794.28,5543.9 2869.28,5543.9 2944.28,5543.9 3019.28,5543.9 3094.28,5543.9 3169.28,5543.9 3244.28,5543.9 3319.28,5543.9 2569.28,5618.9 2644.28,5618.9 2719.28,5618.9 2794.28,5618.9 2869.28,5618.9 2944.28,5618.9 3019.28,5618.9 3094.28,5618.9 3169.28,5618.9 3244.28,5618.9 3319.28,5618.9 3394.28,5618.9 2010.79,5623.5 2085.79,5623.5 2160.79,5623.5 2235.79,5623.5 2644.28,5693.9 2719.28,5693.9 2794.28,5693.9 2869.28,5693.9 2944.28,5693.9 3019.28,5693.9 3094.28,5693.9 3169.28,5693.9 3244.28,5693.9 3319.28,5693.9 3394.28,5693.9 3469.28,5693.9 3544.28,5693.9 3619.28,5693.9 3694.28,5693.9 2085.79,5698.5 2160.79,5698.5 2235.79,5698.5 2160.79,5773.5 3614.28,5843.9 3689.28,5843.9 3614.28,5918.9 3689.28,5918.9 3689.28,5993.9 3534.28,6061.77 3614.28,6068.9 3689.28,6068.9 3614.28,6143.9 3689.28,6143.9 3614.28,6218.9 3689.28,6218.9 3689.28,6293.9 3539.28,6368.9 3614.28,6368.9 3689.28,6368.9 3614.28,6443.9 3689.28,6443.9 3614.28,6518.9 3689.28,6518.9 3689.28,6593.9 3539.28,6668.9 3614.28,6668.9 3689.28,6668.9 3614.28,6743.9 3689.28,6743.9 3614.28,6818.9 3689.28,6818.9 3689.28,6893.9 3539.28,6968.9 3614.28,6968.9 3689.28,6968.9 3614.28,7043.9 3689.28,7043.9 3614.28,7118.9 3689.28,7118.9 3689.28,7193.9 3539.28,7267.95 3614.28,7267.95 3689.28,7267.95 3539.28,7343.9 3614.28,7343.9 3689.28,7343.9
  other v2: 2088.07,2381.46 2139.58,2381.46 2191.09,2381.46 2028.71,2396.79 2061.55,2406.46 2113.07,2406.46 2164.58,2406.46 2216.09,2406.46 1918.04,2428.31 1945.32,2428.31 1973.52,2428.31 2088.07,2431.46 2139.58,2431.46 2191.09,2431.46 1997.48,2432.35 2028.71,2432.35 2061.55,2456.46 2113.07,2456.46 2164.58,2456.46 2216.09,2456.46 1918.04,2462.42 1945.32,2462.42 1973.52,2462.42 1996.73,2462.81 2028.71,2467.91 2088.07,2481.46 2139.58,2481.46 2191.09,2481.46 1996.73,2495.07 1918.04,2497.51 1946.24,2497.51 1973.52,2497.51 2028.71,2503.47 2061.55,2506.46 2113.07,2506.46 2164.58,2506.46 2216.09,2506.46 1996.73,2527.85 1917.94,2531.25 1946.14,2531.25 1973.42,2531.25 2088.07,2531.46 2139.58,2531.46 2191.09,2531.46 2028.71,2539.03 2061.55,2556.46 2113.07,2556.46 2164.58,2556.46 2216.09,2556.46 2088.07,3325.66 2139.58,3325.66 2191.09,3325.66 2028.71,3340.99 2061.55,3350.66 2113.07,3350.66 2164.58,3350.66 2216.09,3350.66 1997.48,3366.55 1918.04,3372.5 1945.32,3372.5 1973.52,3372.5 2088.07,3375.66 2139.58,3375.66 2191.09,3375.66 2028.71,3376.55 1996.73,3397.01 2061.55,3400.66 2113.07,3400.66 2164.58,3400.66 2216.09,3400.66 1918.04,3406.61 1945.32,3406.61 1973.52,3406.61 2028.71,3412.1 2088.07,3425.66 2139.58,3425.66 2191.09,3425.66 1996.73,3429.26 1918.04,3441.71 1946.24,3441.71 1973.52,3441.71 2028.71,3447.66 2061.55,3450.66 2113.07,3450.66 2164.58,3450.66 2216.09,3450.66 1996.73,3462.05 2088.07,3475.66 2139.58,3475.66 2191.09,3475.66 2028.71,3483.22 2061.55,3500.66 2113.07,3500.66 2164.58,3500.66 2216.09,3500.66 2088.07,4269.86 2139.58,4269.86 2191.09,4269.86 2028.71,4285.18 2061.55,4294.86 2113.07,4294.86 2164.58,4294.86 2216.09,4294.86 1918.04,4316.7 1945.32,4316.7 1973.52,4316.7 2088.07,4319.86 2139.58,4319.86 2191.09,4319.86 1997.48,4320.74 2028.71,4320.74 2061.55,4344.86 2113.07,4344.86 2164.58,4344.86 2216.09,4344.86 1918.04,4350.81 1945.32,4350.81 1973.52,4350.81 1996.73,4351.21 2028.71,4356.3 2088.07,4369.86 2139.58,4369.86 2191.09,4369.86 1996.73,4383.46 1918.04,4385.91 1946.24,4385.91 1973.52,4385.91 2028.71,4391.86 2061.55,4394.86 2113.07,4394.86 2164.58,4394.86 2216.09,4394.86 1996.73,4416.24 1917.94,4419.64 1946.14,4419.64 1973.42,4419.64 2088.07,4419.86 2139.58,4419.86 2191.09,4419.86 2028.71,4427.42 2061.55,4444.86 2113.07,4444.86 2164.58,4444.86 2216.09,4444.86 2088.07,5214.05 2139.58,5214.05 2191.09,5214.05 2028.71,5229.38 2061.55,5239.05 2113.07,5239.05 2164.58,5239.05 2216.09,5239.05 1918.04,5260.89 1945.32,5260.89 1973.52,5260.89 1997.48,5264.94 2028.71,5264.94 2088.07,5264.05 2139.58,5264.05 2191.09,5264.05 2061.55,5289.05 2113.07,5289.05 2164.58,5289.05 2216.09,5289.05 1918.04,5295.01 1945.32,5295.01 1973.52,5295.01 1996.73,5295.4 2028.71,5300.5 2088.07,5314.05 2139.58,5314.05 2191.09,5314.05 1996.73,5327.66 1918.04,5330.1 1946.24,5330.1 1973.52,5330.1 2028.71,5336.05 2061.55,5339.05 2113.07,5339.05 2164.58,5339.05 2216.09,5339.05 1996.73,5360.44 1917.94,5363.84 1946.14,5363.84 1973.42,5363.84 2088.07,5364.05 2139.58,5364.05 2191.09,5364.05 2028.71,5371.61 2061.55,5389.05 2113.07,5389.05 2164.58,5389.05 2216.09,5389.05
pads on no net: D1.2 FID5.1 FID5_1.1 FID5_2.1 FID6.1 FID6_1.1 FID6_2.1 H1.1 H2.1 H3.1 H4.1 H5.0 H6.0 H7.0 H8.0 H9.1 H10.1 H11.1 H12.1 H13.0 H14.0 H15.0 H16.0 H17.1 H18.1 H19.0 H20.0 Q8.9@2883.15,6871.69 Q8.9@2883.15,6929.56 Q8.9@2883.15,6987.43 Q8.9@2949.29,6871.69 Q8.9@2949.29,6929.56 Q8.9@2949.29,6987.43 Q9.9@2883.15,7197.75 Q9.9@2883.15,7255.62 Q9.9@2883.15,7313.5 Q9.9@2949.29,7197.75 Q9.9@2949.29,7255.62 Q9.9@2949.29,7313.5 Q10.9@2883.15,6545.62 Q10.9@2883.15,6603.5 Q10.9@2883.15,6661.37 Q10.9@2949.29,6545.62 Q10.9@2949.29,6603.5 Q10.9@2949.29,6661.37 Q11.9@2883.15,6219.56 Q11.9@2883.15,6277.43 Q11.9@2883.15,6335.31 Q11.9@2949.29,6219.56 Q11.9@2949.29,6277.43 Q11.9@2949.29,6335.31 Q12.9@2883.15,5893.5 Q12.9@2883.15,5951.37 Q12.9@2883.15,6009.25 Q12.9@2949.29,5893.5 Q12.9@2949.29,5951.37 Q12.9@2949.29,6009.25 SH1.0 SH2.0 SH3.0 SH4.0 SH5.0 SH6.0 SH7.0 SH8.0 SH9.0 U1.1 U1.2 U1.3 U1.15 U1.16 U2.1 U2.2 U2.3 U2.6 U2.15 U2.16 U3.1 U3.2 U3.3 U3.6 U3.15 U3.16 U4.1 U4.2 U4.3 U4.6 U4.15 U4.16 U5.1 U5.2 U5.3 U5.6 U5.15 U5.16 U6.1 U6.2 U6.3 U6.6 U6.15 U6.16 U9.4

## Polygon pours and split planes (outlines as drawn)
QGND on L9-INT 4 "L9-INT_4_QGND_P1764" (solid, remove dead copper, pour order 1764): 20 vertices, not listed, extent 32.15,2073.9 3388.03,7724.51
PGND on L9-INT 4 "L9-INT_4_PGND_P1761" (solid, remove dead copper, pour order 1761): 72.4,1690.9 3683.4,1690.9 3742.95,1631.34 3742.95,62.57 3709.28,28.9 59.06,28.9 30.45,57.51 30.45,1648.95
VIN on L9-INT 4 "NONET_L-01_P-001" (solid, remove dead copper, pour order 1762): 1843.02,1723.9 93.76,1723.9 36.07,1781.59 36.07,5987.28 64.69,6015.91 900.83,6015.91 1246.7,5670.03 1246.7,2187.78 1385.58,2048.9 1845.75,2048.9 1873.32,2021.32 1873.32,1754.2
VOUT on L9-INT 4 "NONET_L-01_P-001" (solid, remove dead copper, pour order 1763): 1928.41,1723.9 3664.89,1723.9 3748.72,1807.73 3748.72,5771.35 3712.9,5807.18 2903.87,5807.18 2519.28,5422.59 2519.28,2149.07 2419.11,2048.9 1926.3,2048.9 1904.28,2026.88 1904.28,1748.03
VOUT on L9-INT 4 "L9-INT_4_VOUT_P1760" (solid, remove dead copper, pour order 1760): 3295.05,5820.24 3264.28,5851.01 3264.28,7435.56 3279.45,7450.73 3712.58,7450.73 3730.48,7432.83 3730.48,5853.16 3697.57,5820.24
VOUT on L9-INT 4 "NONET_L-01_P-001" (solid, pour order 1636): 1904.38,3487.12 1904.38,3360.24 1921.96,3342.67 2002.31,3342.67 2060.99,3284 2231.91,3284 2263.2,3315.28 2263.2,3530.08 2238.11,3555.17 2046.07,3555.17 1995.98,3505.08 1922.35,3505.08
VIN on L9-INT 4 "NONET_L-01_P-001" (solid, pour order 1633): 1871.48,4290.26 1871.48,4417.13 1853.91,4434.7 1773.55,4434.7 1714.88,4493.38 1487.5,4493.38 1461.52,4467.39 1461.52,4252.8 1492.12,4222.2 1729.79,4222.2 1779.88,4272.29 1853.52,4272.29
VIN on L9-INT 4 "NONET_L-01_P-001" (solid, pour order 1631): 1871.48,5234.45 1871.48,5361.32 1853.91,5378.9 1773.55,5378.9 1714.88,5437.57 1487.5,5437.57 1461.52,5411.59 1461.52,5197 1492.12,5166.4 1729.79,5166.4 1779.88,5216.49 1853.52,5216.49
CSA_IN- on L9-INT 4 "L9-INT_4_CSA_IN-_P1758" (solid, remove dead copper, pour order 1758): 2830.33,7381.78 2867.14,7418.59 3217.93,7418.59 3234.84,7401.68 3234.84,5904.85 3234.84,5893.14 3201.04,5859.33 2852.73,5859.33 2830.33,5881.73
VOUT on L9-INT 4 "NONET_L-01_P-001" (solid, pour order 1757): 1904.38,2542.92 1904.38,2416.05 1921.96,2398.48 2002.31,2398.48 2060.99,2339.8 2231.91,2339.8 2263.2,2371.09 2263.2,2585.89 2238.11,2610.98 2046.07,2610.98 1995.98,2560.89 1922.35,2560.89
VIN on L9-INT 4 "NONET_L-01_P-001" (solid, pour order 1637): 1871.48,2401.86 1871.48,2528.74 1853.91,2546.31 1773.55,2546.31 1714.88,2604.98 1487.5,2604.98 1461.52,2579 1461.52,2364.41 1492.12,2333.81 1729.79,2333.81 1779.88,2383.9 1853.52,2383.9
VIN on L9-INT 4 "NONET_L-01_P-001" (solid, pour order 1635): 1871.48,3346.06 1871.48,3472.93 1853.91,3490.51 1773.55,3490.51 1714.88,3549.18 1487.5,3549.18 1461.52,3523.2 1461.52,3308.61 1492.12,3278.01 1729.79,3278.01 1779.88,3328.09 1853.52,3328.09
VOUT on L9-INT 4 "NONET_L-01_P-001" (solid, pour order 1634): 1904.38,4431.31 1904.38,4304.44 1921.96,4286.87 2002.31,4286.87 2060.99,4228.19 2231.91,4228.19 2263.2,4259.48 2263.2,4474.28 2238.11,4499.37 2046.07,4499.37 1995.98,4449.28 1922.35,4449.28
VOUT on L9-INT 4 "NONET_L-01_P-001" (solid, pour order 1632): 1904.38,5375.51 1904.38,5248.64 1921.96,5231.06 2002.31,5231.06 2060.99,5172.39 2231.91,5172.39 2263.2,5203.67 2263.2,5418.48 2238.11,5443.56 2046.07,5443.56 1995.98,5393.48 1922.35,5393.48
PGND on L9-INT 4 "L9-INT_4_PGND_P1759" (solid, remove dead copper, pour order 1759): 2812.27,5933.3 2802.72,5923.76 2659.73,5923.76 2646,5937.49 2646,7377.51 2661.6,7393.1 2802.45,7393.1 2812.27,7383.28
PGND on Top Layer "TOP_LAYER_PGND_P1575" (solid, remove dead copper, pour order 1575): 24.73,58.24 56.93,26.05 3699.5,26.05 3742.56,69.11 3742.56,1655.35 3687.44,1710.46 79.79,1710.46 24.73,1655.4
QGND on Top Layer "TOP_LAYER_QGND_P1583" (solid, remove dead copper, pour order 1583): 34.07,7565.92 34.07,7650.09 112.88,7728.9 3369.28,7728.9 3389.28,7708.9 3388.03,7707.64 3388.03,7416.49 3368.01,7396.47 2671.74,7396.47 2610.68,7335.4 2610.68,6072.35 2576.61,6038.29 80.18,6038.29 34.07,6084.4
VIN on Top Layer "NONET_L-01_P-001" (solid, remove dead copper, pour order 1863): 33.94,5984.68 73.16,6023.9 1791.9,6023.9 1869.84,5945.95 1869.84,1794.46 1814.28,1738.9 79.28,1738.9 34.28,1783.9 34.28,1793.9 33.94,1794.24
VOUT on Top Layer "NONET_L-01_P-001" (solid, remove dead copper, pour order 1864): 1907.68,5950.97 1907.68,1796.21 1965,1738.9 3669.28,1738.9 3746.33,1815.95 3746.33,5713.7 3703.33,5756.7 3272.92,5756.7 3199.03,5830.59 2768.57,5830.59 2576.89,6022.27 1978.98,6022.27
VOUT on Top Layer "TOP_LAYER_VOUT_P1582" (solid, remove dead copper, pour order 1582): 3289.96,7368.5 3702.36,7368.5 3742.29,7328.56 3742.29,5842.94 3711.49,5812.14 3318.84,5812.14 3269.28,5861.7 3269.28,7347.82
PGND on Top Layer "TOP_LAYER_PGND_P1580" (solid, remove dead copper, pour order 1580): 2644.33,6390.56 2644.33,6483.61 2657.67,6496.95 2785.7,6496.95 2799.12,6483.53 2799.12,6246 2789.68,6236.56 2653.85,6236.56 2644.33,6246.08
PGND on Top Layer "TOP_LAYER_PGND_P1578" (solid, remove dead copper, pour order 1578): 2644.33,6716.62 2644.33,6809.67 2657.67,6823.01 2785.7,6823.01 2798.81,6809.9 2798.81,6570.93 2790.51,6562.62 2653.85,6562.62 2644.33,6572.14
PGND on Top Layer "TOP_LAYER_PGND_P1577" (solid, remove dead copper, pour order 1577): 2644.33,7135.73 2657.67,7149.07 2785.7,7149.07 2798.54,7136.24 2798.54,6895.11 2792.12,6888.69 2661.18,6888.69 2644.33,6905.54
VOUT on Top Layer "NONET_L-01_P-001" (solid, remove dead copper, pour order 1841): 2004.95,2402.94 2039.3,2368.59 2377.66,2368.59 2403.85,2394.78 2403.85,2611.63 2387.76,2627.72 2073.05,2627.72 1986.84,2541.51 1912.93,2541.51 1907.68,2536.27 1907.68,2408.29 1913.03,2402.94
VOUT on Top Layer "TOP_LAYER_VOUT_P1840" (solid, remove dead copper, pour order 1840): 2039.17,2368.72 2376.92,2368.72 2403.85,2395.65 2403.85,2611.63 2387.76,2627.72 2073.05,2627.72 1986.84,2541.56 1912.54,2541.56 1907.88,2536.91 1907.88,2408.09 1913.03,2402.94 2004.95,2402.94
VOUT on Top Layer "TOP_LAYER_VOUT_P1839" (solid, remove dead copper, pour order 1839): 1986.84,2541.51 2072.39,2627.06 2145.31,2627.06 2173.3,2599.08 2173.3,2401.96 2139.92,2368.59 2039.04,2368.59 2004.49,2403.14 1913.03,2402.94 1907.88,2408.09 1907.88,2536.91 1912.48,2541.51
VOUT on Top Layer "NONET_L-01_P-001" (solid, remove dead copper, pour order 1838): 2387.84,3572.54 2077.34,3572.54 1989.03,3484.23 1915.11,3484.23 1909.87,3478.99 1909.87,3351.01 1915.22,3345.66 2007.14,3345.66 2096.37,3256.43 2096.37,3128.96 2136.3,3089.03 2366.47,3089.03 2406.04,3128.6 2406.04,3554.35
VOUT on Top Layer "TOP_LAYER_VOUT_P1837" (solid, remove dead copper, pour order 1837): 2041.36,3311.44 2379.11,3311.44 2406.04,3338.37 2406.04,3554.35 2389.94,3570.44 2075.24,3570.44 1989.03,3484.28 1914.72,3484.28 1910.07,3479.63 1910.07,3350.81 1915.22,3345.66 2007.14,3345.66
VOUT on Top Layer "TOP_LAYER_VOUT_P1836" (solid, remove dead copper, pour order 1836): 1989.03,3484.23 2074.58,3569.78 2147.5,3569.78 2175.49,3541.8 2175.49,3344.68 2142.11,3311.31 2041.23,3311.31 2006.68,3345.86 1915.22,3345.66 1910.07,3350.81 1910.07,3479.63 1914.67,3484.23
VOUT on Top Layer "NONET_L-01_P-001" (solid, remove dead copper, pour order 1835): 2387.76,4516.11 2073.05,4516.11 1986.84,4429.9 1912.93,4429.9 1907.68,4424.66 1907.68,4296.68 1913.03,4291.33 2004.95,4291.33 2094.18,4202.1 2094.18,4074.63 2134.11,4034.7 2364.28,4034.7 2403.85,4074.27 2403.85,4500.02
VOUT on Top Layer "TOP_LAYER_VOUT_P1834" (solid, remove dead copper, pour order 1834): 2039.17,4257.11 2376.92,4257.11 2403.85,4284.04 2403.85,4500.02 2387.76,4516.11 2073.05,4516.11 1986.84,4429.96 1912.54,4429.96 1907.88,4425.3 1907.88,4296.48 1913.03,4291.33 2004.95,4291.33
VOUT on Top Layer "TOP_LAYER_VOUT_P1833" (solid, remove dead copper, pour order 1833): 1986.84,4429.9 2072.39,4515.45 2145.31,4515.45 2173.3,4487.47 2173.3,4290.36 2139.92,4256.98 2039.04,4256.98 2004.49,4291.53 1913.03,4291.33 1907.88,4296.48 1907.88,4425.3 1912.48,4429.9
VOUT on Top Layer "NONET_L-01_P-001" (solid, remove dead copper, pour order 1329): 2387.76,5460.31 2073.05,5460.31 1986.84,5374.1 1912.93,5374.1 1907.68,5368.85 1907.68,5240.87 1913.03,5235.53 2004.95,5235.53 2094.18,5146.3 2094.18,5018.82 2134.11,4978.9 2364.28,4978.9 2403.85,5018.46 2403.85,5444.22
VIN on Top Layer "TOP_LAYER_VIN_P1312" (solid, remove dead copper, pour order 1312): 1785.72,5373.86 1756.66,5402.93 1641.82,5402.93 1625.35,5386.45 1625.35,5206.86 1640.58,5191.63 1728.93,5191.63 1768.75,5231.45 1866.37,5231.24 1869.65,5234.51 1869.65,5371.26 1867.04,5373.86
VIN on Top Layer "TOP_LAYER_VIN_P1700" (solid, remove dead copper, pour order 1700): 1869.65,2402.96 1869.65,2537.05 1866.97,2539.73 1763.98,2539.73 1699.87,2603.84 1113.35,2603.84 1059.63,2550.12 880.5,2550.12 875.36,2544.99 875.36,2366.6 883.23,2358.73 1728.63,2358.73 1768.69,2398.79 1865.48,2398.79
VIN on Top Layer "TOP_LAYER_VIN_P1699" (solid, remove dead copper, pour order 1699): 1866.81,2539.75 1763.96,2539.75 1699.87,2603.84 1336.85,2603.84 1318.92,2585.91 1318.92,2382.73 1342.92,2358.73 1728.63,2358.73 1768.64,2398.75 1865.43,2398.75 1869.65,2402.96 1869.65,2536.91
VIN on Top Layer "TOP_LAYER_VIN_P1698" (solid, remove dead copper, pour order 1698): 19 vertices, not listed, extent 875.36,3302.93 1869.65,3559.02
VIN on Top Layer "TOP_LAYER_VIN_P1697" (solid, remove dead copper, pour order 1697): 1866.86,3485.54 1770.88,3485.54 1697.4,3559.02 1640.11,3559.02 1630.46,3549.37 1338.18,3549.37 1318.92,3530.11 1318.92,3326.93 1342.92,3302.93 1728.63,3302.93 1771.19,3345.5 1867.99,3345.5 1869.65,3347.16 1869.65,3482.75
VIN on Top Layer "TOP_LAYER_VIN_P1696" (solid, remove dead copper, pour order 1696): 17 vertices, not listed, extent 875.36,4247.13 1869.65,4515.88
VIN on Top Layer "TOP_LAYER_VIN_P1695" (solid, remove dead copper, pour order 1695): 1318.92,4474.3 1318.92,4271.12 1342.92,4247.13 1728.63,4247.13 1770.03,4288.53 1866.83,4288.53 1869.65,4291.36 1869.65,4425.3 1868.29,4426.66 1783.19,4426.66 1693.97,4515.88 1360.49,4515.88
VIN on Top Layer "TOP_LAYER_VIN_P1693" (solid, remove dead copper, pour order 1693): 17 vertices, not listed, extent 875.36,5191.32 1869.65,5460.07
CSA_IN- on Top Layer "TOP_LAYER_CSA_IN-_P1581" (solid, remove dead copper, pour order 1581): 3234.84,7172.88 3234.84,7335.08 3201.43,7368.5 2863.16,7368.5 2837.25,7342.59 2837.25,5855.84 2846.59,5846.5 3213.94,5846.5 3234.84,5867.4
PGND on Top Layer "TOP_LAYER_PGND_P1579" (solid, remove dead copper, pour order 1579): 2657.11,5910.5 2793.75,5910.5 2802.98,5919.73 2802.98,6148.63 2787.71,6163.9 2654.87,6163.9 2644.33,6153.35 2644.33,5923.28
PGND on Top Layer "TOP_LAYER_PGND_P1576" (solid, remove dead copper, pour order 1576): 2673.85,7214.75 2791.07,7214.75 2798.49,7222.17 2798.49,7372.89 2788.64,7382.75 2666.97,7382.75 2660.13,7375.91 2660.13,7228.47
PGND on Top Layer "NONET_L-01_P-001" (solid, remove dead copper, pour order 1574): 2391.4,5488.69 2391.4,5566.72 2377.64,5580.48 2250.09,5580.48 2237.1,5567.49 2237.1,5488.79 2241.96,5483.93 2386.64,5483.93
VIN on Top Layer "NONET_L-01_P-001" (solid, remove dead copper, pour order 647): 1255.6,6055.76 1188.32,6055.76 1168.54,6075.54 1168.54,6150.15 1183.01,6164.61 1248.01,6164.61 1254.98,6157.65 1254.98,6103.91 1260.72,6098.16 1260.72,6060.88
VIN on Top Layer "TOP_LAYER_VIN_P1324" (solid, remove dead copper, pour order 1324): 1763.98,2539.83 1737.81,2566 1646.71,2566 1625.35,2544.63 1625.35,2366.77 1633.35,2358.77 1728.67,2358.77 1770.12,2400.23 1866.73,2400.02 1869.65,2402.94 1869.65,2536.91 1866.72,2539.83
VOUT on Top Layer "TOP_LAYER_VOUT_P1315" (solid, remove dead copper, pour order 1315): 2039.17,5201.31 2376.92,5201.31 2403.85,5228.23 2403.85,5444.22 2387.76,5460.31 2073.05,5460.31 1986.84,5374.15 1912.54,5374.15 1907.88,5369.49 1907.88,5240.68 1913.03,5235.53 2004.95,5235.53
VOUT on Top Layer "TOP_LAYER_VOUT_P1313" (solid, remove dead copper, pour order 1313): 1986.84,5374.1 2072.39,5459.65 2145.31,5459.65 2173.3,5431.66 2173.3,5234.55 2139.92,5201.18 2039.04,5201.18 2004.49,5235.73 1913.03,5235.53 1907.88,5240.68 1907.88,5369.49 1912.48,5374.1
+5V on Top Layer "TOP_LAYER_+5V_P1277" (solid, remove dead copper, pour order 1277): 18 vertices, not listed, extent 2474.54,6828.9 2556.31,6938.9
NetR33_1 on Top Layer "TOP_LAYER_NETR33_1_P1271" (solid, remove dead copper, pour order 1271): 2534.28,5826.66 2642.05,5826.66 2644.28,5828.9 2644.28,5890.85 2636.23,5898.9 2542.33,5898.9 2531.49,5888.06 2531.49,5829.46
+5V on Top Layer "TOP_LAYER_+5V_P1071" (solid, remove dead copper, pour order 1071): 1203.49,6308.03 1212.7,6317.24 1249.29,6317.24 1258.49,6308.04 1258.49,6188.83 1255.49,6185.83 1206.49,6185.83 1203.49,6188.83
+5V on Top Layer "TOP_LAYER_+5V_P927" (solid, remove dead copper, pour order 927): 2606.28,5815.5 2609.28,5812.5 2609.28,5757.45 2559.33,5707.5 2515.33,5707.5 2514.33,5708.5 2514.33,5799.5 2530.33,5815.5
QGND on L6-INT 1 "L6-INT_1_QGND_P1616" (solid, remove dead copper, pour order 1616): 29.23,7526.81 221.32,7718.9 3379.28,7718.9 3389.28,7708.9 3389.28,7429.51 3373.67,7413.9 2676.68,7413.9 2654.12,7391.34 2654.12,6100.03 2585.13,6031.04 82.37,6031.04 29.23,6081.96
PGND on L6-INT 1 "L6-INT_1_PGND_P1615" (solid, remove dead copper, pour order 1615): 26.96,56.7 55.66,28 3703.56,28 3746.15,70.6 3746.15,1660.54 3715.79,1690.9 48.73,1690.9 26.96,1669.12
VIN on L6-INT 1 "L6-INT_1_VIN_P1823" (solid, remove dead copper, pour order 1823): 76.04,1723.9 1835.41,1723.9 1873.32,1761.8 1873.32,5995.34 1850.52,6018.73 73.45,6018.73 28.38,5973.66 28.38,1771.56
VOUT on L6-INT 1 "L6-INT_1_VOUT_P1822" (solid, remove dead copper, pour order 1822): 1931.67,6018 2533.6,6018 2737.97,5813.63 3701.12,5813.63 3753.65,5761.09 3753.65,1751.37 3726.18,1723.9 1941.76,1723.9 1904.28,1761.37 1904.28,5990.62
VOUT on L6-INT 1 "L6-INT_1_VOUT_P1610" (solid, remove dead copper, pour order 1610): 3380.94,7387.36 3721.81,7387.36 3744.28,7364.89 3744.28,5854.53 3713.49,5823.73 3391.9,5823.73 3359.28,5856.35 3359.28,7365.7
VOUT on L6-INT 1 "NONET_L-01_P-001" (solid, pour order 1730): 1904.38,3487.12 1904.38,3360.24 1921.96,3342.67 2002.31,3342.67 2060.99,3284 2231.91,3284 2263.2,3315.28 2263.2,3530.08 2238.11,3555.17 2046.07,3555.17 1995.98,3505.08 1922.35,3505.08
PGND on L6-INT 1 "L6-INT_1_PGND_P1612" (solid, remove dead copper, pour order 1612): 2843.98,5931.08 2823.92,5911.02 2681.1,5911.02 2669.47,5922.65 2669.47,7376.14 2688.81,7395.49 2821.74,7395.49 2843.98,7373.25
VOUT on L6-INT 1 "NONET_L-01_P-001" (solid, pour order 1732): 1904.38,2542.92 1904.38,2416.05 1921.96,2398.48 2002.31,2398.48 2060.99,2339.8 2231.91,2339.8 2263.2,2371.09 2263.2,2585.89 2238.11,2610.98 2046.07,2610.98 1995.98,2560.89 1922.35,2560.89
VIN on L6-INT 1 "NONET_L-01_P-001" (solid, pour order 1731): 1871.48,2401.86 1871.48,2528.74 1853.91,2546.31 1773.55,2546.31 1714.88,2604.98 1487.5,2604.98 1461.52,2579 1461.52,2364.41 1492.12,2333.81 1729.79,2333.81 1779.88,2383.9 1853.52,2383.9
VIN on L6-INT 1 "NONET_L-01_P-001" (solid, pour order 1729): 1871.48,3346.06 1871.48,3472.93 1853.91,3490.51 1773.55,3490.51 1714.88,3549.18 1487.5,3549.18 1461.52,3523.2 1461.52,3308.61 1492.12,3278.01 1729.79,3278.01 1779.88,3328.09 1853.52,3328.09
